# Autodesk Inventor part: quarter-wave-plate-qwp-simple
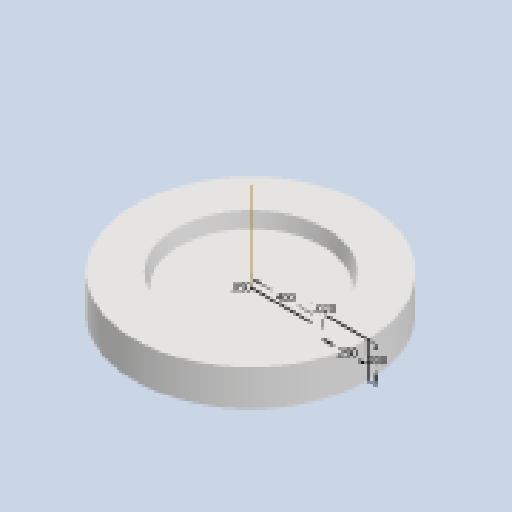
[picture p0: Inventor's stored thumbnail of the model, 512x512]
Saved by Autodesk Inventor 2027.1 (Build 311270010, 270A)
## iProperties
Created: 2026-07
Part Number: quarter-wave-plate-qwp-simple
Material: Generic
Document SubType Name: Modeling
Designer: dunge
Density: 1 g/cm^3
Appearance: Default
Author: dunge
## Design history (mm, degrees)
sketch "Sketch1"
  geometry: L1 (0, 0.635)-(10.16, 0.635); L2 (10.16, 0.635)-(10.16, -0.635); L3 (10.16, -0.635)-(0, -0.635); L4 (0, -0.635)-(0, 0.635); L5 (0, 0.635)-(10.16, -0.635); L6 (10.16, 0.635)-(0, -0.635); L7 (10.16, 0.635)-(10.668, 2.54); L8 (10.668, 2.54)-(16.51, 2.54); L9 (16.51, 2.54)-(16.51, -2.54); L10 (16.51, -2.54)-(10.668, -2.54); L11 (10.668, -2.54)-(10.16, -0.635); 3 further points
  constraints: 22 end point, 3 midpoint, 3 perpendicular, 2 horizontal, 2 parallel, 1 coincident, 1 equal length, 1 vertical alignment
  dimensions: "d0" = 1.27 distance of L3.end L1.start; "d1" = 10.16 distance of L1.start L1.end; "d2" = 5.08 distance of L8.end L9.end; "d3" = 0.508 horizontal distance of L1.end L7.end; "d4" = 6.35 distance between parallel lines of L9 L2
revolve "Revolution1" stored, may be unused: angle "d5" = 360 deg
workpoint "Work Point1"
  workaxis "Work Axis1"
body "Solid1"
